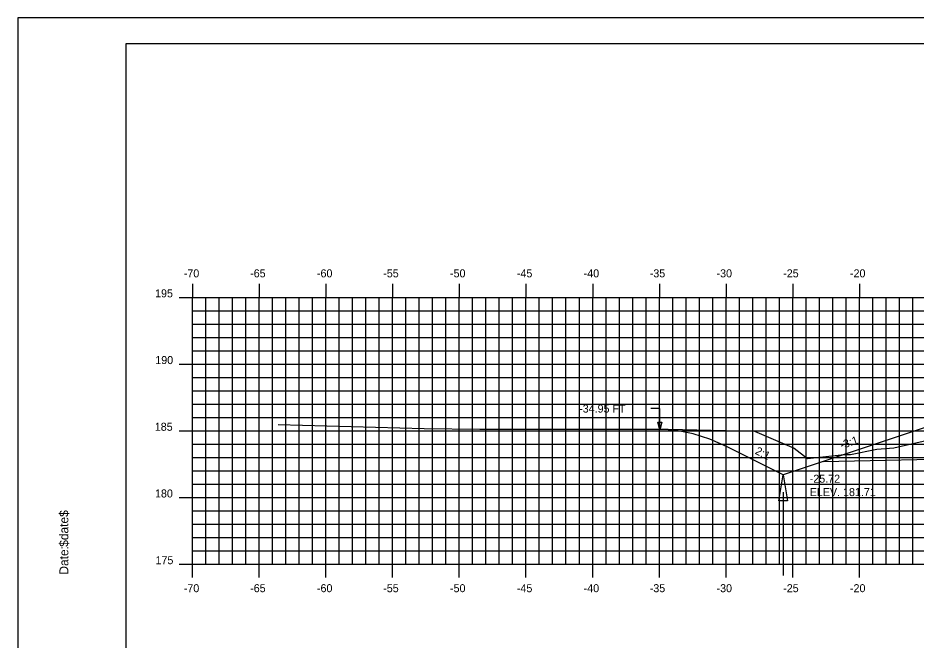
# Model space of a CAD drawing. Extents: x 1139650 to 1139820, y 608981 to 609091.
# Drawn here: x 1139650.1 to 1139717.5, y 609044.6 to 609091.3 of the extents above; entities that cross this region are included whole.
import ezdxf

# ---------------------------------------------------------------- set-up
doc = ezdxf.new("R2010")
doc.units = 0
for name, color, linetype in [('ANNOTATION', 7, 'Continuous'), ('BORDER', 7, 'Continuous'), ('D_Drainage_Ditch_Line', 7, 'Continuous'), ('D_Roadway_SlopeLines', 7, 'Continuous'), ('D_Roadway_SubGrade', 7, 'Continuous'), ('D_Text_Standard', 7, 'Continuous'), ('H_V ANNOTATION', 7, 'Continuous'), ('MAJOR', 7, 'Continuous'), ('MINOR', 7, 'Continuous'), ('PLOT BOUNDARY', 7, 'Continuous'), ('S_Roadway_Centerline', 7, 'Continuous')]:
    doc.layers.add(name, color=color, linetype=linetype)

msp = doc.modelspace()

# ---------------------------------------------------------------- linework, layer by layer
at = {"layer": 'BORDER'}
msp.add_lwpolyline([(1139658.219, 608984.335), (1139818.219, 608984.335), (1139818.219, 609089.335), (1139658.219, 609089.335)], close=True, dxfattribs=at)
at = {"layer": 'D_Drainage_Ditch_Line'}
msp.add_line((1139707.494, 609055.729), (1139707.493, 609049.486), dxfattribs=at)
msp.add_lwpolyline([(1139707.822, 609055.073), (1139707.166, 609055.073), (1139707.494, 609057.041)], close=True, dxfattribs=at)
at = {"layer": 'D_Roadway_SlopeLines'}
for points in [[(1139707.494, 609057.041), (1139703.265, 609059.156), (1139702.015, 609059.705), (1139700.765, 609060.105), (1139699.515, 609060.353), (1139698.265, 609060.452)], [(1139710.494, 609058.041), (1139707.494, 609057.041)]]:
    msp.add_lwpolyline(points, dxfattribs=at)
at = {"layer": 'D_Roadway_SubGrade'}
msp.add_lwpolyline([(1139722.218, 609060.359), (1139722.218, 609060.526), (1139718.218, 609060.366), (1139718.218, 609060.616), (1139718.217, 609060.616), (1139710.494, 609058.041), (1139722.218, 609058.276)], close=True, dxfattribs=at)
at = {"layer": 'D_Text_Standard'}
msp.add_lwpolyline([(1139698.265, 609060.406), (1139698.255, 609061.995), (1139697.575, 609061.995)], dxfattribs=at)
msp.add_lwpolyline([(1139698.265, 609060.406), (1139698.116, 609060.987), (1139698.407, 609060.989)], close=True, dxfattribs=at)
at = {"layer": 'MAJOR'}
for p, q in [((1139663.218, 609071.337), (1139663.218, 609070.335)), ((1139668.218, 609071.337), (1139668.218, 609070.335)), ((1139673.218, 609071.337), (1139673.218, 609070.335)), ((1139678.218, 609071.337), (1139678.218, 609070.335)), ((1139683.218, 609071.337), (1139683.218, 609070.335)), ((1139688.218, 609071.337), (1139688.218, 609070.335)), ((1139693.218, 609071.337), (1139693.218, 609070.335)), ((1139698.218, 609071.337), (1139698.218, 609070.335)), ((1139703.218, 609071.337), (1139703.218, 609070.335)), ((1139708.218, 609071.337), (1139708.218, 609070.335)), ((1139713.218, 609071.337), (1139713.218, 609070.335)), ((1139662.216, 609070.335), (1139663.218, 609070.335)), ((1139663.218, 609070.335), (1139803.218, 609070.335)), ((1139663.218, 609050.335), (1139663.218, 609070.335)), ((1139663.218, 609050.335), (1139663.218, 609070.335)), ((1139663.218, 609070.335), (1139803.218, 609070.335)), ((1139668.218, 609050.335), (1139668.218, 609070.335)), ((1139673.218, 609050.335), (1139673.218, 609070.335)), ((1139678.218, 609050.335), (1139678.218, 609070.335)), ((1139683.218, 609050.335), (1139683.218, 609070.335)), ((1139688.218, 609050.335), (1139688.218, 609070.335)), ((1139693.218, 609050.335), (1139693.218, 609070.335)), ((1139698.218, 609050.335), (1139698.218, 609070.335)), ((1139703.218, 609050.335), (1139703.218, 609070.335)), ((1139708.218, 609050.335), (1139708.218, 609070.335)), ((1139713.218, 609050.335), (1139713.218, 609070.335)), ((1139662.216, 609065.335), (1139663.218, 609065.335)), ((1139663.218, 609065.335), (1139803.218, 609065.335)), ((1139662.216, 609060.335), (1139663.218, 609060.335)), ((1139663.218, 609060.335), (1139803.218, 609060.335)), ((1139662.216, 609055.335), (1139663.218, 609055.335)), ((1139663.218, 609055.335), (1139803.218, 609055.335)), ((1139662.216, 609050.335), (1139663.218, 609050.335)), ((1139663.218, 609050.335), (1139803.218, 609050.335)), ((1139663.218, 609050.335), (1139803.218, 609050.335)), ((1139663.218, 609049.333), (1139663.218, 609050.335)), ((1139668.218, 609049.333), (1139668.218, 609050.335)), ((1139673.218, 609049.333), (1139673.218, 609050.335)), ((1139678.218, 609049.333), (1139678.218, 609050.335)), ((1139683.218, 609049.333), (1139683.218, 609050.335)), ((1139688.218, 609049.333), (1139688.218, 609050.335)), ((1139693.218, 609049.333), (1139693.218, 609050.335)), ((1139698.218, 609049.333), (1139698.218, 609050.335)), ((1139703.218, 609049.333), (1139703.218, 609050.335)), ((1139708.218, 609049.333), (1139708.218, 609050.335)), ((1139713.218, 609049.333), (1139713.218, 609050.335))]:
    msp.add_line(p, q, dxfattribs=at)
at = {"layer": 'MINOR'}
for p, q in [((1139664.218, 609050.335), (1139664.218, 609070.335)), ((1139665.218, 609050.335), (1139665.218, 609070.335)), ((1139666.218, 609050.335), (1139666.218, 609070.335)), ((1139667.218, 609050.335), (1139667.218, 609070.335)), ((1139669.218, 609050.335), (1139669.218, 609070.335)), ((1139670.218, 609050.335), (1139670.218, 609070.335)), ((1139671.218, 609050.335), (1139671.218, 609070.335)), ((1139672.218, 609050.335), (1139672.218, 609070.335)), ((1139674.218, 609050.335), (1139674.218, 609070.335)), ((1139675.218, 609050.335), (1139675.218, 609070.335)), ((1139676.218, 609050.335), (1139676.218, 609070.335)), ((1139677.218, 609050.335), (1139677.218, 609070.335)), ((1139679.218, 609050.335), (1139679.218, 609070.335)), ((1139680.218, 609050.335), (1139680.218, 609070.335)), ((1139681.218, 609050.335), (1139681.218, 609070.335)), ((1139682.218, 609050.335), (1139682.218, 609070.335)), ((1139684.218, 609050.335), (1139684.218, 609070.335)), ((1139685.218, 609050.335), (1139685.218, 609070.335)), ((1139686.218, 609050.335), (1139686.218, 609070.335)), ((1139687.218, 609050.335), (1139687.218, 609070.335)), ((1139689.218, 609050.335), (1139689.218, 609070.335)), ((1139690.218, 609050.335), (1139690.218, 609070.335)), ((1139691.218, 609050.335), (1139691.218, 609070.335)), ((1139692.218, 609050.335), (1139692.218, 609070.335)), ((1139694.218, 609050.335), (1139694.218, 609070.335)), ((1139695.218, 609050.335), (1139695.218, 609070.335)), ((1139696.218, 609050.335), (1139696.218, 609070.335)), ((1139697.218, 609050.335), (1139697.218, 609070.335)), ((1139699.218, 609050.335), (1139699.218, 609070.335)), ((1139700.218, 609050.335), (1139700.218, 609070.335)), ((1139701.218, 609050.335), (1139701.218, 609070.335)), ((1139702.218, 609050.335), (1139702.218, 609070.335)), ((1139704.218, 609050.335), (1139704.218, 609070.335)), ((1139705.218, 609050.335), (1139705.218, 609070.335)), ((1139706.218, 609050.335), (1139706.218, 609070.335)), ((1139707.218, 609050.335), (1139707.218, 609070.335)), ((1139709.218, 609050.335), (1139709.218, 609070.335)), ((1139710.218, 609050.335), (1139710.218, 609070.335)), ((1139711.218, 609050.335), (1139711.218, 609070.335)), ((1139712.218, 609050.335), (1139712.218, 609070.335)), ((1139714.218, 609050.335), (1139714.218, 609070.335)), ((1139715.218, 609050.335), (1139715.218, 609070.335)), ((1139716.218, 609050.335), (1139716.218, 609070.335)), ((1139717.218, 609050.335), (1139717.218, 609070.335)), ((1139663.218, 609069.335), (1139803.218, 609069.335)), ((1139663.218, 609069.335), (1139664.22, 609069.335)), ((1139663.218, 609068.335), (1139803.218, 609068.335)), ((1139663.218, 609068.335), (1139664.22, 609068.335)), ((1139663.218, 609067.335), (1139803.218, 609067.335)), ((1139663.218, 609067.335), (1139664.22, 609067.335)), ((1139663.218, 609066.335), (1139803.218, 609066.335)), ((1139663.218, 609066.335), (1139664.22, 609066.335)), ((1139663.218, 609064.335), (1139803.218, 609064.335)), ((1139663.218, 609064.335), (1139664.22, 609064.335)), ((1139663.218, 609063.335), (1139803.218, 609063.335)), ((1139663.218, 609063.335), (1139664.22, 609063.335)), ((1139663.218, 609062.335), (1139803.218, 609062.335)), ((1139663.218, 609062.335), (1139664.22, 609062.335)), ((1139663.218, 609061.335), (1139803.218, 609061.335)), ((1139663.218, 609061.335), (1139664.22, 609061.335)), ((1139663.218, 609059.335), (1139803.218, 609059.335)), ((1139663.218, 609059.335), (1139664.22, 609059.335)), ((1139663.218, 609058.335), (1139803.218, 609058.335)), ((1139663.218, 609058.335), (1139664.22, 609058.335)), ((1139663.218, 609057.335), (1139803.218, 609057.335)), ((1139663.218, 609057.335), (1139664.22, 609057.335)), ((1139663.218, 609056.335), (1139803.218, 609056.335)), ((1139663.218, 609056.335), (1139664.22, 609056.335)), ((1139663.218, 609054.335), (1139803.218, 609054.335)), ((1139663.218, 609054.335), (1139664.22, 609054.335)), ((1139663.218, 609053.335), (1139803.218, 609053.335)), ((1139663.218, 609053.335), (1139664.22, 609053.335)), ((1139663.218, 609052.335), (1139803.218, 609052.335)), ((1139663.218, 609052.335), (1139664.22, 609052.335)), ((1139663.218, 609051.335), (1139803.218, 609051.335)), ((1139663.218, 609051.335), (1139664.22, 609051.335))]:
    msp.add_line(p, q, dxfattribs=at)
at = {"layer": 'PLOT BOUNDARY'}
msp.add_lwpolyline([(1139650.125, 608981.276), (1139820.125, 608981.276), (1139820.125, 609091.276), (1139650.125, 609091.276)], close=True, dxfattribs=at)
at = {"layer": 'S_Roadway_Centerline'}
msp.add_lwpolyline([(1139669.647, 609060.798), (1139680.586, 609060.506), (1139684.759, 609060.449), (1139698.877, 609060.452), (1139705.352, 609060.294), (1139705.354, 609060.302), (1139708.327, 609059.029), (1139709.33, 609058.253), (1139712.066, 609058.546), (1139712.562, 609058.546), (1139714.521, 609058.948), (1139715.804, 609059.061), (1139723.951, 609060.903)], dxfattribs=at)

# ---------------------------------------------------------------- texts
at = {"layer": 'ANNOTATION'}
for s, rotation, p in [('-3:1', 18.43482, (1139711.873, 609058.955)), ('2:1', 333.43495, (1139705.346, 609058.633))]:
    msp.add_text(s, height=0.6, rotation=rotation, dxfattribs=at).set_placement(p)
at = {"layer": 'BORDER'}
for s, p in [('$date$', (1139653.903, 609051.64)), ('Date:', (1139653.903, 609049.552))]:
    msp.add_text(s, height=0.6696, rotation=90, dxfattribs=at).set_placement(p)
at = {"layer": 'D_Text_Standard'}
for s, p in [('-34.95 FT', (1139692.205, 609061.695)), ('-25.72', (1139709.494, 609056.441)), ('ELEV. 181.71', (1139709.494, 609055.439))]:
    msp.add_text(s, height=0.6, dxfattribs=at).set_placement(p)
at = {"layer": 'H_V ANNOTATION'}
for s, p in [('-70', (1139662.56, 609071.835)), ('-65', (1139667.536, 609071.835)), ('-60', (1139672.544, 609071.835)), ('-55', (1139677.514, 609071.835)), ('-50', (1139682.522, 609071.835)), ('-45', (1139687.536, 609071.835)), ('-40', (1139692.544, 609071.835)), ('-35', (1139697.498, 609071.835)), ('-30', (1139702.507, 609071.835)), ('-25', (1139707.504, 609071.835)), ('-20', (1139712.512, 609071.835)), ('195', (1139660.407, 609070.335)), ('190', (1139660.423, 609065.335)), ('185', (1139660.386, 609060.335)), ('180', (1139660.402, 609055.335)), ('175', (1139660.439, 609050.335)), ('-70', (1139662.56, 609048.235)), ('-65', (1139667.536, 609048.235)), ('-60', (1139672.544, 609048.235)), ('-55', (1139677.514, 609048.235)), ('-50', (1139682.522, 609048.235)), ('-45', (1139687.536, 609048.235)), ('-40', (1139692.544, 609048.235)), ('-35', (1139697.498, 609048.235)), ('-30', (1139702.507, 609048.235)), ('-25', (1139707.504, 609048.235)), ('-20', (1139712.512, 609048.235))]:
    msp.add_text(s, height=0.6, dxfattribs=at).set_placement(p)
at = {"layer": 'MAJOR'}
msp.add_text('-', height=0.006, dxfattribs=at).set_placement((1139663.214, 609050.335))

doc.saveas('drawing.dxf')
